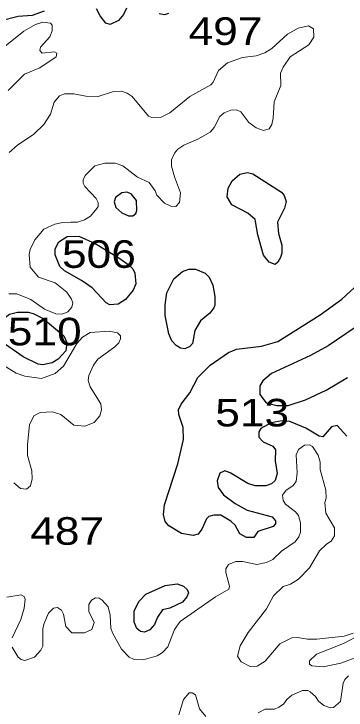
# Model space of a CAD drawing. Extents: x 577 to 602.9, y 7483.8 to 7511.6.
# Drawn here: x 593.996 to 594.959, y 7498.704 to 7500.722 of the extents above; entities that cross this region are included whole.
import ezdxf
from ezdxf.enums import TextEntityAlignment as Align

# ---------------------------------------------------------------- set-up
doc = ezdxf.new("R2010")
doc.units = 0
doc.header["$LTSCALE"] = 0.032
doc.layers.add('1', color=7, linetype='Continuous', lineweight=25)
doc.layers.add('2', color=7, linetype='Continuous', lineweight=13)
doc.layers.add('61', color=7, linetype='Continuous')

msp = doc.modelspace()

# ---------------------------------------------------------------- linework, layer by layer
at = {"layer": '1'}
for points in [[(594.0838, 7500.7305), (594.0496, 7500.7178), (594.0083, 7500.7146), (593.955, 7500.7011), (593.9327, 7500.6876), (593.9144, 7500.6661), (593.8993, 7500.6542), (593.8055, 7500.6375), (593.7761, 7500.6248), (593.7475, 7500.5985), (593.7125, 7500.5842), (593.6791, 7500.5771), (593.6441, 7500.5779), (593.6011, 7500.5882), (593.5518, 7500.6129), (593.5383, 7500.6296), (593.5336, 7500.6407), (593.5344, 7500.6542)], [(594.3224, 7500.7393), (594.3136, 7500.721), (594.2993, 7500.7035), (594.2755, 7500.6916), (594.2627, 7500.6956), (594.246, 7500.717), (594.2357, 7500.7369)], [(594.4448, 7500.7234), (594.4329, 7500.7194), (594.417, 7500.7226)], [(594.9465, 7499.8958), (595.0078, 7499.9513)], [(594.6373, 7499.2404), (594.6253, 7499.2523), (594.5959, 7499.269), (594.576, 7499.2698), (594.5617, 7499.265), (594.5546, 7499.2587), (594.541, 7499.2285), (594.5307, 7499.2141), (594.5164, 7499.2102), (594.4822, 7499.2165), (594.4456, 7499.238), (594.4345, 7499.2507), (594.4297, 7499.2714), (594.4329, 7499.2992), (594.4711, 7499.4185), (594.4878, 7499.4885), (594.487, 7499.5235), (594.4742, 7499.5616), (594.4735, 7499.5744), (594.4814, 7499.5911), (594.5061, 7499.6237), (594.5299, 7499.6682), (594.5649, 7499.704), (594.6182, 7499.7405), (594.6412, 7499.7509), (594.7144, 7499.7596), (594.7613, 7499.7731), (594.8838, 7499.8503), (594.9465, 7499.8958)], [(594.9824, 7499.8113), (594.9076, 7499.7604), (594.8559, 7499.7318), (594.743, 7499.6801), (594.7176, 7499.6586), (594.7088, 7499.6443), (594.7096, 7499.6188), (594.7277, 7499.5951), (594.7583, 7499.5868), (594.7917, 7499.5868), (594.8418, 7499.6035), (594.9013, 7499.6316), (594.9633, 7499.6682)], [(594.9617, 7499.4988), (594.9331, 7499.529), (594.9172, 7499.5251), (594.8917, 7499.4964), (594.8814, 7499.498), (594.8424, 7499.5211), (594.7963, 7499.541), (594.774, 7499.5425), (594.7422, 7499.537), (594.712, 7499.5203), (594.7064, 7499.5107), (594.7064, 7499.4956), (594.7192, 7499.4821), (594.747, 7499.4694), (594.7542, 7499.4591), (594.7534, 7499.4265), (594.7597, 7499.3899), (594.7534, 7499.37), (594.743, 7499.3605), (594.7271, 7499.3541), (594.6961, 7499.3541), (594.6746, 7499.3612), (594.6237, 7499.3923), (594.6078, 7499.3978), (594.5935, 7499.3915), (594.5856, 7499.3692), (594.5888, 7499.3493), (594.6039, 7499.3278), (594.6373, 7499.3032), (594.6722, 7499.2841), (594.7454, 7499.2642), (594.7542, 7499.2531), (594.7542, 7499.2444), (594.7478, 7499.2364), (594.7033, 7499.2221), (594.6921, 7499.2046), (594.6707, 7499.2046), (594.6508, 7499.2157), (594.6373, 7499.2404)]]:
    msp.add_lwpolyline(points, dxfattribs=at)
for points in [[(594.7201, 7500.0231), (594.7033, 7500.0817), (594.6953, 7500.1262), (594.6746, 7500.1445), (594.6277, 7500.1684), (594.6142, 7500.1922), (594.6174, 7500.2169), (594.6293, 7500.2383), (594.6516, 7500.2574), (594.6738, 7500.263), (594.6889, 7500.259), (594.7716, 7500.2057), (594.7796, 7500.1962), (594.7852, 7500.1787), (594.7804, 7500.1588), (594.7605, 7500.1183), (594.7637, 7500.0857), (594.7732, 7500.0523), (594.7732, 7500.0284), (594.7693, 7500.0165), (594.7613, 7500.0022), (594.7534, 7499.9958), (594.7359, 7500.003)], [(594.2918, 7500.161), (594.3096, 7500.1461), (594.3287, 7500.1365), (594.3415, 7500.1373), (594.3494, 7500.1437), (594.3526, 7500.1524), (594.3518, 7500.1811), (594.3367, 7500.201), (594.324, 7500.2057), (594.3096, 7500.2041), (594.2906, 7500.1898), (594.2866, 7500.1779)], [(594.1269, 7500.0614), (594.1509, 7500.0767), (594.185, 7500.0781), (594.2323, 7500.0572), (594.3009, 7500.0149), (594.3303, 7499.9942), (594.3415, 7499.9831), (594.347, 7499.9711), (594.3502, 7499.9401), (594.3422, 7499.9211), (594.32, 7499.894), (594.2985, 7499.8813), (594.2747, 7499.8789), (594.2635, 7499.8845), (594.223, 7499.9282), (594.192, 7499.9497), (594.1427, 7499.9775), (594.1299, 7499.9902), (594.1164, 7500.0244), (594.1164, 7500.0411)], [(594.4395, 7499.9139), (594.4599, 7499.9544), (594.4846, 7499.9759), (594.5037, 7499.9823), (594.5228, 7499.9823), (594.5506, 7499.9711), (594.5625, 7499.9592), (594.5729, 7499.9362), (594.5792, 7499.9028), (594.5792, 7499.8781), (594.576, 7499.8702), (594.5641, 7499.8551), (594.5371, 7499.8328), (594.5212, 7499.8042), (594.514, 7499.7668), (594.5061, 7499.758), (594.4917, 7499.7517), (594.479, 7499.7533), (594.4663, 7499.7612), (594.4544, 7499.7747), (594.4456, 7499.7946), (594.4345, 7499.8479), (594.4345, 7499.8789)], [(594.0814, 7499.8395), (594.1411, 7499.7891), (594.1498, 7499.77), (594.1466, 7499.7461), (594.1244, 7499.7215), (594.1077, 7499.7111), (594.0798, 7499.7048), (594.0663, 7499.7071), (594.0234, 7499.7286), (593.9622, 7499.7708), (593.9502, 7499.7906), (593.9486, 7499.8129), (593.9637, 7499.8368), (593.9836, 7499.8519), (594.0067, 7499.8582), (594.0377, 7499.8574), (594.052, 7499.8543)], [(594.3787, 7499.04), (594.4345, 7499.0654), (594.4695, 7499.0702), (594.4878, 7499.0631), (594.4981, 7499.0543), (594.5021, 7499.044), (594.4973, 7499.0328), (594.4846, 7499.0169), (594.4488, 7498.9994), (594.4273, 7498.9947), (594.413, 7498.974), (594.4043, 7498.9525), (594.39, 7498.9374), (594.3749, 7498.9303), (594.3637, 7498.9319), (594.3526, 7498.9406), (594.3446, 7498.9589), (594.3454, 7498.9915), (594.3589, 7499.0193)]]:
    msp.add_lwpolyline(points, close=True, dxfattribs=at)
at = {"layer": '2'}
for points in [[(593.9796, 7500.5007), (594.0266, 7500.5476), (594.0719, 7500.5659), (594.1188, 7500.5977), (594.1204, 7500.6081), (594.114, 7500.6121), (594.0783, 7500.6089), (594.0711, 7500.616), (594.0735, 7500.6256), (594.1005, 7500.6558), (594.1077, 7500.6733), (594.1069, 7500.69), (594.1021, 7500.6956), (594.0806, 7500.6987), (594.0592, 7500.6916), (594.025, 7500.6725), (593.951, 7500.6136)], [(594.3884, 7500.2336), (594.4059, 7500.2097), (594.4106, 7500.197), (594.4329, 7500.1739), (594.4512, 7500.1652), (594.4655, 7500.1636), (594.4766, 7500.1755), (594.479, 7500.2033), (594.4615, 7500.2503), (594.4536, 7500.2813), (594.4536, 7500.2996), (594.4623, 7500.3186), (594.4719, 7500.3298), (594.4886, 7500.3417), (594.5291, 7500.3592), (594.5649, 7500.3799), (594.5768, 7500.3934), (594.5935, 7500.4244), (594.6062, 7500.4355), (594.6253, 7500.4435), (594.642, 7500.4443), (594.654, 7500.4387), (594.677, 7500.4077), (594.6985, 7500.3918), (594.72, 7500.3846), (594.7367, 7500.3894), (594.7438, 7500.4013), (594.7478, 7500.4196), (594.751, 7500.4673), (594.7701, 7500.515), (594.7693, 7500.5508), (594.7764, 7500.5683), (594.7971, 7500.5977), (594.8512, 7500.6327), (594.8655, 7500.655), (594.8647, 7500.6789), (594.8504, 7500.6876), (594.8201, 7500.6812), (594.7891, 7500.6637), (594.7438, 7500.6216), (594.7239, 7500.6097), (594.6985, 7500.6009), (594.6587, 7500.5962), (594.6158, 7500.5803), (594.5895, 7500.558), (594.5744, 7500.5246), (594.5673, 7500.5166), (594.5061, 7500.4832), (594.4488, 7500.4355), (594.4234, 7500.4228), (594.3963, 7500.422), (594.3868, 7500.426), (594.3391, 7500.4832), (594.3248, 7500.4928), (594.3081, 7500.4983), (594.2826, 7500.4968), (594.2405, 7500.4832), (594.2047, 7500.484), (594.1697, 7500.4904), (594.1427, 7500.4904), (594.1283, 7500.4848), (594.1132, 7500.4665), (594.1021, 7500.4316), (594.083, 7500.4021), (594.0544, 7500.3735), (594.0067, 7500.3417), (593.9828, 7500.321)], [(593.982, 7499.9107), (594.0051, 7499.9107), (594.0449, 7499.8948), (594.0854, 7499.8662), (594.118, 7499.8527), (594.1358, 7499.8518), (594.1522, 7499.8586), (594.164, 7499.8719), (594.1669, 7499.8849), (594.1633, 7499.8956), (594.1498, 7499.9155), (594.1164, 7499.9425), (594.0679, 7499.9592), (594.0433, 7499.9878), (594.0401, 7500.0252), (594.0433, 7500.0395), (594.0568, 7500.0674), (594.0835, 7500.0986), (594.1154, 7500.1131), (594.1383, 7500.1179), (594.1617, 7500.1186), (594.1804, 7500.1183), (594.2006, 7500.1249), (594.2185, 7500.1363), (594.2368, 7500.1578), (594.2402, 7500.1641), (594.2402, 7500.1756), (594.2344, 7500.1871), (594.2015, 7500.2216), (594.1975, 7500.2312), (594.1975, 7500.2415), (594.2031, 7500.2542), (594.2309, 7500.2821), (594.2596, 7500.2892), (594.2898, 7500.2892), (594.312, 7500.2821), (594.3542, 7500.2495), (594.3884, 7500.2336)], [(593.9963, 7499.3628), (594.0154, 7499.3469), (594.0329, 7499.3445), (594.0441, 7499.3541), (594.0496, 7499.3748), (594.048, 7499.3978), (594.0353, 7499.4424), (594.0353, 7499.4742), (594.0417, 7499.5314), (594.0544, 7499.5569), (594.0727, 7499.5672), (594.1069, 7499.5688), (594.1323, 7499.5608), (594.1697, 7499.5298), (594.2015, 7499.5274), (594.2293, 7499.5378), (594.2452, 7499.5577), (594.25, 7499.5744), (594.2484, 7499.5918), (594.2174, 7499.6411), (594.2118, 7499.6594), (594.2134, 7499.6738), (594.2269, 7499.704), (594.2397, 7499.7215), (594.289, 7499.7572), (594.3009, 7499.7692), (594.3057, 7499.7803), (594.3057, 7499.7891), (594.2969, 7499.7978), (594.2725, 7499.8029), (594.2172, 7499.7986), (594.1951, 7499.7851), (594.1784, 7499.7668), (594.1403, 7499.7016), (594.1156, 7499.6801), (594.0759, 7499.6658), (594.0282, 7499.6722), (594.0027, 7499.6809), (593.9622, 7499.7056)], [(594.98, 7498.9271), (594.9537, 7498.9183), (594.8742, 7498.9104), (594.8472, 7498.9104), (594.8186, 7498.9152), (594.8019, 7498.9136), (594.7669, 7498.8961), (594.7247, 7498.846), (594.7017, 7498.8317), (594.681, 7498.8309), (594.6548, 7498.8444), (594.6444, 7498.8603), (594.6524, 7498.8905), (594.6754, 7498.9295), (594.7287, 7498.9979), (594.7486, 7499.0352), (594.7764, 7499.0623), (594.7979, 7499.0694), (594.8217, 7499.0837), (594.8528, 7499.1171), (594.8822, 7499.1664), (594.9021, 7499.1855), (594.9164, 7499.1943), (594.9259, 7499.2094), (594.9259, 7499.2324), (594.9005, 7499.2754), (594.8981, 7499.3064), (594.9013, 7499.3183), (594.9005, 7499.3422), (594.8846, 7499.4018), (594.8846, 7499.4225), (594.8782, 7499.4431), (594.8623, 7499.4686), (594.8528, 7499.4734), (594.8384, 7499.4718), (594.8217, 7499.4598), (594.8146, 7499.4439), (594.8178, 7499.3923), (594.8146, 7499.3668), (594.805, 7499.3541), (594.786, 7499.3414), (594.7748, 7499.3271), (594.7772, 7499.3119), (594.7836, 7499.3016), (594.813, 7499.2793), (594.8209, 7499.2682), (594.8273, 7499.2467), (594.8273, 7499.2205), (594.8225, 7499.2062), (594.8114, 7499.1919), (594.7716, 7499.1648), (594.747, 7499.141), (594.7287, 7499.1322), (594.7001, 7499.1267), (594.6587, 7499.1346), (594.6396, 7499.1346), (594.6182, 7499.1259), (594.611, 7499.1139), (594.611, 7499.1036), (594.6214, 7499.0639), (594.619, 7499.0551), (594.5808, 7499.0328), (594.4782, 7498.9613)], [(593.9916, 7498.9136), (594.0162, 7498.9668), (594.0258, 7499.0002), (594.0289, 7499.0257), (594.0258, 7499.0336), (594.017, 7499.0384), (593.9757, 7499.032)], [(594.4782, 7498.9613), (594.4623, 7498.9382), (594.4424, 7498.8881), (594.4273, 7498.8714), (594.4114, 7498.8619), (594.3709, 7498.8499), (594.343, 7498.8515), (594.3303, 7498.8579), (594.3081, 7498.881), (594.2818, 7498.9279), (594.277, 7498.9422), (594.2755, 7498.9796), (594.2699, 7499.0034), (594.2524, 7499.0233), (594.2436, 7499.0289), (594.2325, 7499.0297), (594.2214, 7499.0233), (594.2134, 7499.0106), (594.2134, 7498.9899), (594.2293, 7498.9581), (594.2222, 7498.9382), (594.2007, 7498.9279), (594.1641, 7498.9287), (594.1466, 7498.947), (594.1403, 7498.9827), (594.1347, 7498.9939), (594.1228, 7499.0018), (594.1109, 7498.9994), (594.0965, 7498.9851), (594.083, 7498.9533), (594.0798, 7498.9398), (594.0798, 7498.8897), (594.0743, 7498.8778), (594.056, 7498.8579), (594.0282, 7498.8484), (594.017, 7498.8507), (594.0083, 7498.8579), (593.9908, 7498.8865)], [(595.2305, 7498.9478), (594.9442, 7498.8404), (594.8925, 7498.8293), (594.8599, 7498.8325), (594.8528, 7498.8372), (594.8535, 7498.8476), (594.8734, 7498.8666), (594.9514, 7498.8977), (594.9903, 7498.9175)], [(594.8329, 7498.7609), (594.848, 7498.7609), (594.8551, 7498.7569), (594.8702, 7498.7434), (594.879, 7498.7299), (594.8949, 7498.7172), (594.914, 7498.7108), (594.9227, 7498.7116), (594.9434, 7498.7291), (594.9506, 7498.7824), (594.9553, 7498.7935), (594.9665, 7498.8038)], [(594.4742, 7498.6909), (594.4878, 7498.7354), (594.5045, 7498.7545), (594.5132, 7498.7545), (594.5228, 7498.7482), (594.5347, 7498.7076), (594.553, 7498.6853)], [(594.7048, 7498.6965), (594.7247, 7498.7068), (594.7518, 7498.7068), (594.7645, 7498.7124), (594.778, 7498.7219), (594.7875, 7498.7354), (594.8019, 7498.7474), (594.8329, 7498.7609)]]:
    msp.add_lwpolyline(points, dxfattribs=at)

# ---------------------------------------------------------------- texts
at = {"layer": '61', "width": 1.2}
for s, p in [('497', (594.6096, 7500.6323)), ('506', (594.2428, 7499.9861)), ('510', (594.0856, 7499.7615)), ('513', (594.687, 7499.5265)), ('487', (594.1507, 7499.1835))]:
    msp.add_text(s, height=0.08, dxfattribs=at).set_placement(p, align=Align.CENTER)

doc.saveas('drawing.dxf')
